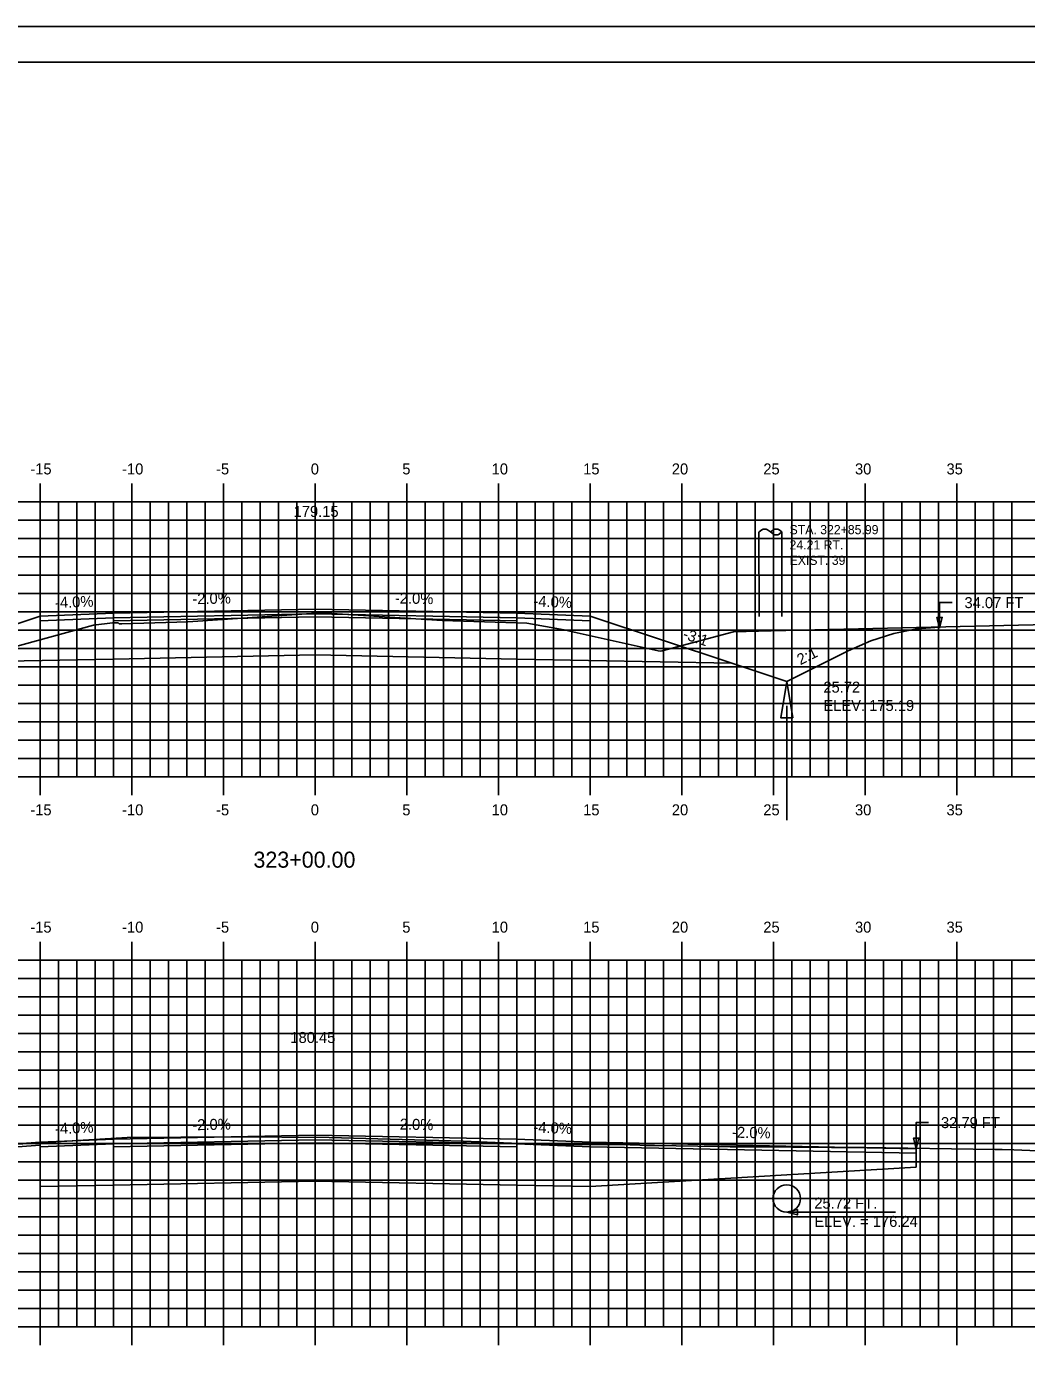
# Model space of a CAD drawing. Extents: x 1140094 to 1140264, y 608981 to 609091.
# Drawn here: x 1140161 to 1140215.5, y 609019.1 to 609091.3 of the extents above; entities that cross this region are included whole.
import ezdxf

# ---------------------------------------------------------------- set-up
doc = ezdxf.new("R2010")
doc.units = 0
for name, color, linetype in [('ANNOTATION', 7, 'Continuous'), ('BORDER', 7, 'Continuous'), ('D_Drainage_Culvert', 7, 'Continuous'), ('D_Drainage_Ditch_Line', 7, 'Continuous'), ('D_Roadway_Centerline', 7, 'Continuous'), ('D_Roadway_Centerline_Text', 7, 'Continuous'), ('D_Roadway_Edge_Shoulder', 7, 'Continuous'), ('D_Roadway_Edge_TW', 7, 'Continuous'), ('D_Roadway_Pavement', 7, 'Continuous'), ('D_Roadway_SlopeLines', 7, 'Continuous'), ('D_Roadway_SubGrade', 7, 'Continuous'), ('D_Text_Monospaced', 7, 'Continuous'), ('D_Text_Standard', 7, 'Continuous'), ('H_V ANNOTATION', 7, 'Continuous'), ('MAJOR', 7, 'Continuous'), ('MINOR', 7, 'Continuous'), ('PLOT BOUNDARY', 7, 'Continuous'), ('S_Roadway_Centerline', 7, 'Continuous'), ('S_Utilities_Pole_Power', 7, 'Continuous')]:
    doc.layers.add(name, color=color, linetype=linetype)

msp = doc.modelspace()

# ---------------------------------------------------------------- linework, layer by layer
for points in [[(1140146.431, 609056.645), (1140147.575, 609056.586), (1140148.719, 609056.38), (1140149.863, 609056.028), (1140151.007, 609055.529), (1140154.007, 609056.529), (1140161.73, 609059.104), (1140161.731, 609059.104), (1140165.731, 609059.264), (1140176.731, 609059.484), (1140187.731, 609059.264), (1140191.731, 609059.104), (1140199.455, 609056.529), (1140202.455, 609055.529), (1140205.798, 609057.201), (1140207.048, 609057.751), (1140208.298, 609058.153), (1140209.548, 609058.405), (1140210.798, 609058.508)], [(1140161.73, 609030.403), (1140161.731, 609030.403), (1140165.731, 609030.563), (1140176.731, 609030.783), (1140187.731, 609030.563), (1140191.731, 609030.403), (1140209.522, 609030.047)]]:
    msp.add_lwpolyline(points)
at = {"layer": 'BORDER'}
msp.add_lwpolyline([(1140101.732, 608984.335), (1140261.732, 608984.335), (1140261.732, 609089.335), (1140101.732, 609089.335)], close=True, dxfattribs=at)
at = {"layer": 'D_Drainage_Culvert'}
msp.add_circle((1140202.455, 609027.329), 0.75, dxfattribs=at)
at = {"layer": 'D_Drainage_Ditch_Line'}
msp.add_line((1140202.455, 609054.217), (1140202.455, 609047.974), dxfattribs=at)
msp.add_lwpolyline([(1140202.783, 609053.561), (1140202.127, 609053.561), (1140202.455, 609055.529)], close=True, dxfattribs=at)
at = {"layer": 'D_Roadway_Edge_Shoulder'}
for points in [[(1140165.731, 609059.264), (1140161.731, 609059.104), (1140161.731, 609058.854), (1140165.731, 609059.014)], [(1140187.731, 609059.264), (1140191.731, 609059.104), (1140191.731, 609058.854), (1140187.731, 609059.014)], [(1140165.731, 609030.563), (1140161.731, 609030.403), (1140161.731, 609030.153), (1140165.731, 609030.313)], [(1140187.731, 609030.563), (1140191.731, 609030.403), (1140191.731, 609030.153), (1140187.731, 609030.313)], [(1140161.731, 609030.403), (1140158.731, 609030.183), (1140158.744, 609030.016), (1140161.73, 609030.236)], [(1140191.731, 609030.403), (1140191.731, 609030.153), (1140209.522, 609029.797), (1140209.522, 609030.047)]]:
    msp.add_lwpolyline(points, close=True, dxfattribs=at)
at = {"layer": 'D_Roadway_Edge_TW'}
for points in [[(1140165.731, 609059.014), (1140165.731, 609059.264), (1140176.731, 609059.484), (1140187.731, 609059.264), (1140187.731, 609059.014), (1140176.731, 609059.234)], [(1140165.731, 609030.313), (1140165.731, 609030.563), (1140176.731, 609030.783), (1140187.731, 609030.563), (1140187.731, 609030.313), (1140176.731, 609030.533)]]:
    msp.add_lwpolyline(points, close=True, dxfattribs=at)
at = {"layer": 'D_Roadway_Pavement'}
for points in [[(1140165.731, 609058.847), (1140165.731, 609059.014), (1140176.731, 609059.234), (1140187.731, 609059.014), (1140187.731, 609058.847), (1140176.731, 609059.067)], [(1140165.731, 609030.146), (1140165.731, 609030.313), (1140176.731, 609030.533), (1140187.731, 609030.313), (1140187.731, 609030.146), (1140176.731, 609030.366)]]:
    msp.add_lwpolyline(points, close=True, dxfattribs=at)
at = {"layer": 'D_Roadway_SlopeLines'}
for points in [[(1140202.455, 609055.529), (1140205.798, 609057.201), (1140207.048, 609057.751), (1140208.298, 609058.153), (1140209.548, 609058.405), (1140210.798, 609058.508)], [(1140199.455, 609056.529), (1140202.455, 609055.529)]]:
    msp.add_lwpolyline(points, dxfattribs=at)
at = {"layer": 'D_Roadway_SubGrade'}
for points in [[(1140165.731, 609058.847), (1140165.731, 609059.014), (1140161.731, 609058.854), (1140161.731, 609059.104), (1140161.73, 609059.104), (1140154.007, 609056.529), (1140165.731, 609056.764)], [(1140165.731, 609056.764), (1140165.731, 609058.847), (1140176.731, 609059.067), (1140187.731, 609058.847), (1140187.731, 609056.764), (1140176.731, 609056.984)], [(1140187.731, 609058.847), (1140187.731, 609059.014), (1140191.731, 609058.854), (1140191.731, 609059.104), (1140191.732, 609059.104), (1140199.455, 609056.529), (1140187.731, 609056.764)], [(1140161.73, 609029.403), (1140161.731, 609027.983), (1140165.731, 609028.063), (1140165.731, 609030.146), (1140165.731, 609030.313), (1140161.731, 609030.153), (1140161.731, 609030.403), (1140161.73, 609030.403)], [(1140165.731, 609028.063), (1140165.731, 609030.146), (1140176.731, 609030.366), (1140187.731, 609030.146), (1140187.731, 609028.063), (1140176.731, 609028.283)], [(1140209.522, 609029.047), (1140209.522, 609030.047), (1140191.731, 609030.403), (1140191.731, 609030.153), (1140187.731, 609030.313), (1140187.731, 609030.146), (1140187.731, 609028.063), (1140191.731, 609027.983)]]:
    msp.add_lwpolyline(points, close=True, dxfattribs=at)
at = {"layer": 'D_Text_Standard'}
msp.add_line((1140203.961, 609026.579), (1140208.398, 609026.579), dxfattribs=at)
for points in [[(1140210.798, 609058.451), (1140210.792, 609059.84), (1140211.472, 609059.84)], [(1140209.522, 609030.047), (1140209.512, 609031.469), (1140210.192, 609031.469)], [(1140202.455, 609026.579), (1140203.281, 609026.579), (1140203.961, 609026.579)]]:
    msp.add_lwpolyline(points, dxfattribs=at)
for points in [[(1140210.798, 609058.451), (1140210.65, 609059.032), (1140210.941, 609059.034)], [(1140209.522, 609030.047), (1140209.373, 609030.628), (1140209.664, 609030.63)], [(1140202.455, 609026.579), (1140203.037, 609026.724), (1140203.037, 609026.433)]]:
    msp.add_lwpolyline(points, close=True, dxfattribs=at)
at = {"layer": 'MAJOR'}
for p, q in [((1140161.731, 609066.337), (1140161.731, 609065.335)), ((1140166.731, 609066.337), (1140166.731, 609065.335)), ((1140171.731, 609066.337), (1140171.731, 609065.335)), ((1140176.731, 609066.337), (1140176.731, 609065.335)), ((1140181.731, 609066.337), (1140181.731, 609065.335)), ((1140186.731, 609066.337), (1140186.731, 609065.335)), ((1140191.731, 609066.337), (1140191.731, 609065.335)), ((1140196.731, 609066.337), (1140196.731, 609065.335)), ((1140201.731, 609066.337), (1140201.731, 609065.335)), ((1140206.731, 609066.337), (1140206.731, 609065.335)), ((1140211.731, 609066.337), (1140211.731, 609065.335)), ((1140106.731, 609065.335), (1140246.731, 609065.335)), ((1140106.731, 609065.335), (1140246.731, 609065.335)), ((1140161.731, 609050.335), (1140161.731, 609065.335)), ((1140166.731, 609050.335), (1140166.731, 609065.335)), ((1140171.731, 609050.335), (1140171.731, 609065.335)), ((1140176.731, 609050.335), (1140176.731, 609065.335)), ((1140181.731, 609050.335), (1140181.731, 609065.335)), ((1140186.731, 609050.335), (1140186.731, 609065.335)), ((1140191.731, 609050.335), (1140191.731, 609065.335)), ((1140196.731, 609050.335), (1140196.731, 609065.335)), ((1140201.731, 609050.335), (1140201.731, 609065.335)), ((1140206.731, 609050.335), (1140206.731, 609065.335)), ((1140211.731, 609050.335), (1140211.731, 609065.335)), ((1140106.731, 609060.335), (1140246.731, 609060.335)), ((1140106.731, 609055.335), (1140246.731, 609055.335)), ((1140106.731, 609050.335), (1140246.731, 609050.335)), ((1140106.731, 609050.335), (1140246.731, 609050.335)), ((1140161.731, 609049.333), (1140161.731, 609050.335)), ((1140166.731, 609049.333), (1140166.731, 609050.335)), ((1140171.731, 609049.333), (1140171.731, 609050.335)), ((1140176.731, 609049.333), (1140176.731, 609050.335)), ((1140181.731, 609049.333), (1140181.731, 609050.335)), ((1140186.731, 609049.333), (1140186.731, 609050.335)), ((1140191.731, 609049.333), (1140191.731, 609050.335)), ((1140196.731, 609049.333), (1140196.731, 609050.335)), ((1140201.731, 609049.333), (1140201.731, 609050.335)), ((1140206.731, 609049.333), (1140206.731, 609050.335)), ((1140211.731, 609049.333), (1140211.731, 609050.335)), ((1140161.731, 609041.337), (1140161.731, 609040.335)), ((1140166.731, 609041.337), (1140166.731, 609040.335)), ((1140171.731, 609041.337), (1140171.731, 609040.335)), ((1140176.731, 609041.337), (1140176.731, 609040.335)), ((1140181.731, 609041.337), (1140181.731, 609040.335)), ((1140186.731, 609041.337), (1140186.731, 609040.335)), ((1140191.731, 609041.337), (1140191.731, 609040.335)), ((1140196.731, 609041.337), (1140196.731, 609040.335)), ((1140201.731, 609041.337), (1140201.731, 609040.335)), ((1140206.731, 609041.337), (1140206.731, 609040.335)), ((1140211.731, 609041.337), (1140211.731, 609040.335)), ((1140106.731, 609040.335), (1140246.731, 609040.335)), ((1140106.731, 609040.335), (1140246.731, 609040.335)), ((1140161.731, 609020.335), (1140161.731, 609040.335)), ((1140166.731, 609020.335), (1140166.731, 609040.335)), ((1140171.731, 609020.335), (1140171.731, 609040.335)), ((1140176.731, 609020.335), (1140176.731, 609040.335)), ((1140181.731, 609020.335), (1140181.731, 609040.335)), ((1140186.731, 609020.335), (1140186.731, 609040.335)), ((1140191.731, 609020.335), (1140191.731, 609040.335)), ((1140196.731, 609020.335), (1140196.731, 609040.335)), ((1140201.731, 609020.335), (1140201.731, 609040.335)), ((1140206.731, 609020.335), (1140206.731, 609040.335)), ((1140211.731, 609020.335), (1140211.731, 609040.335)), ((1140106.731, 609035.335), (1140246.731, 609035.335)), ((1140106.731, 609030.335), (1140246.731, 609030.335)), ((1140106.731, 609025.335), (1140246.731, 609025.335)), ((1140106.731, 609020.335), (1140246.731, 609020.335)), ((1140106.731, 609020.335), (1140246.731, 609020.335)), ((1140161.731, 609019.333), (1140161.731, 609020.335)), ((1140166.731, 609019.333), (1140166.731, 609020.335)), ((1140171.731, 609019.333), (1140171.731, 609020.335)), ((1140176.731, 609019.333), (1140176.731, 609020.335)), ((1140181.731, 609019.333), (1140181.731, 609020.335)), ((1140186.731, 609019.333), (1140186.731, 609020.335)), ((1140191.731, 609019.333), (1140191.731, 609020.335)), ((1140196.731, 609019.333), (1140196.731, 609020.335)), ((1140201.731, 609019.333), (1140201.731, 609020.335)), ((1140206.731, 609019.333), (1140206.731, 609020.335)), ((1140211.731, 609019.333), (1140211.731, 609020.335))]:
    msp.add_line(p, q, dxfattribs=at)
at = {"layer": 'MINOR'}
for p, q in [((1140162.731, 609050.335), (1140162.731, 609065.335)), ((1140163.731, 609050.335), (1140163.731, 609065.335)), ((1140164.731, 609050.335), (1140164.731, 609065.335)), ((1140165.731, 609050.335), (1140165.731, 609065.335)), ((1140167.731, 609050.335), (1140167.731, 609065.335)), ((1140168.731, 609050.335), (1140168.731, 609065.335)), ((1140169.731, 609050.335), (1140169.731, 609065.335)), ((1140170.731, 609050.335), (1140170.731, 609065.335)), ((1140172.731, 609050.335), (1140172.731, 609065.335)), ((1140173.731, 609050.335), (1140173.731, 609065.335)), ((1140174.731, 609050.335), (1140174.731, 609065.335)), ((1140175.731, 609050.335), (1140175.731, 609065.335)), ((1140177.731, 609050.335), (1140177.731, 609065.335)), ((1140178.731, 609050.335), (1140178.731, 609065.335)), ((1140179.731, 609050.335), (1140179.731, 609065.335)), ((1140180.731, 609050.335), (1140180.731, 609065.335)), ((1140182.731, 609050.335), (1140182.731, 609065.335)), ((1140183.731, 609050.335), (1140183.731, 609065.335)), ((1140184.731, 609050.335), (1140184.731, 609065.335)), ((1140185.731, 609050.335), (1140185.731, 609065.335)), ((1140187.731, 609050.335), (1140187.731, 609065.335)), ((1140188.731, 609050.335), (1140188.731, 609065.335)), ((1140189.731, 609050.335), (1140189.731, 609065.335)), ((1140190.731, 609050.335), (1140190.731, 609065.335)), ((1140192.731, 609050.335), (1140192.731, 609065.335)), ((1140193.731, 609050.335), (1140193.731, 609065.335)), ((1140194.731, 609050.335), (1140194.731, 609065.335)), ((1140195.731, 609050.335), (1140195.731, 609065.335)), ((1140197.731, 609050.335), (1140197.731, 609065.335)), ((1140198.731, 609050.335), (1140198.731, 609065.335)), ((1140199.731, 609050.335), (1140199.731, 609065.335)), ((1140200.731, 609050.335), (1140200.731, 609065.335)), ((1140202.731, 609050.335), (1140202.731, 609065.335)), ((1140203.731, 609050.335), (1140203.731, 609065.335)), ((1140204.731, 609050.335), (1140204.731, 609065.335)), ((1140205.731, 609050.335), (1140205.731, 609065.335)), ((1140207.731, 609050.335), (1140207.731, 609065.335)), ((1140208.731, 609050.335), (1140208.731, 609065.335)), ((1140209.731, 609050.335), (1140209.731, 609065.335)), ((1140210.731, 609050.335), (1140210.731, 609065.335)), ((1140212.731, 609050.335), (1140212.731, 609065.335)), ((1140213.731, 609050.335), (1140213.731, 609065.335)), ((1140214.731, 609050.335), (1140214.731, 609065.335)), ((1140106.731, 609064.335), (1140246.731, 609064.335)), ((1140106.731, 609063.335), (1140246.731, 609063.335)), ((1140106.731, 609062.335), (1140246.731, 609062.335)), ((1140106.731, 609061.335), (1140246.731, 609061.335)), ((1140106.731, 609059.335), (1140246.731, 609059.335)), ((1140106.731, 609058.335), (1140246.731, 609058.335)), ((1140106.731, 609057.335), (1140246.731, 609057.335)), ((1140106.731, 609056.335), (1140246.731, 609056.335)), ((1140106.731, 609054.335), (1140246.731, 609054.335)), ((1140106.731, 609053.335), (1140246.731, 609053.335)), ((1140106.731, 609052.335), (1140246.731, 609052.335)), ((1140106.731, 609051.335), (1140246.731, 609051.335)), ((1140162.731, 609020.335), (1140162.731, 609040.335)), ((1140163.731, 609020.335), (1140163.731, 609040.335)), ((1140164.731, 609020.335), (1140164.731, 609040.335)), ((1140165.731, 609020.335), (1140165.731, 609040.335)), ((1140167.731, 609020.335), (1140167.731, 609040.335)), ((1140168.731, 609020.335), (1140168.731, 609040.335)), ((1140169.731, 609020.335), (1140169.731, 609040.335)), ((1140170.731, 609020.335), (1140170.731, 609040.335)), ((1140172.731, 609020.335), (1140172.731, 609040.335)), ((1140173.731, 609020.335), (1140173.731, 609040.335)), ((1140174.731, 609020.335), (1140174.731, 609040.335)), ((1140175.731, 609020.335), (1140175.731, 609040.335)), ((1140177.731, 609020.335), (1140177.731, 609040.335)), ((1140178.731, 609020.335), (1140178.731, 609040.335)), ((1140179.731, 609020.335), (1140179.731, 609040.335)), ((1140180.731, 609020.335), (1140180.731, 609040.335)), ((1140182.731, 609020.335), (1140182.731, 609040.335)), ((1140183.731, 609020.335), (1140183.731, 609040.335)), ((1140184.731, 609020.335), (1140184.731, 609040.335)), ((1140185.731, 609020.335), (1140185.731, 609040.335)), ((1140187.731, 609020.335), (1140187.731, 609040.335)), ((1140188.731, 609020.335), (1140188.731, 609040.335)), ((1140189.731, 609020.335), (1140189.731, 609040.335)), ((1140190.731, 609020.335), (1140190.731, 609040.335)), ((1140192.731, 609020.335), (1140192.731, 609040.335)), ((1140193.731, 609020.335), (1140193.731, 609040.335)), ((1140194.731, 609020.335), (1140194.731, 609040.335)), ((1140195.731, 609020.335), (1140195.731, 609040.335)), ((1140197.731, 609020.335), (1140197.731, 609040.335)), ((1140198.731, 609020.335), (1140198.731, 609040.335)), ((1140199.731, 609020.335), (1140199.731, 609040.335)), ((1140200.731, 609020.335), (1140200.731, 609040.335)), ((1140202.731, 609020.335), (1140202.731, 609040.335)), ((1140203.731, 609020.335), (1140203.731, 609040.335)), ((1140204.731, 609020.335), (1140204.731, 609040.335)), ((1140205.731, 609020.335), (1140205.731, 609040.335)), ((1140207.731, 609020.335), (1140207.731, 609040.335)), ((1140208.731, 609020.335), (1140208.731, 609040.335)), ((1140209.731, 609020.335), (1140209.731, 609040.335)), ((1140210.731, 609020.335), (1140210.731, 609040.335)), ((1140212.731, 609020.335), (1140212.731, 609040.335)), ((1140213.731, 609020.335), (1140213.731, 609040.335)), ((1140214.731, 609020.335), (1140214.731, 609040.335)), ((1140106.731, 609039.335), (1140246.731, 609039.335)), ((1140106.731, 609038.335), (1140246.731, 609038.335)), ((1140106.731, 609037.335), (1140246.731, 609037.335)), ((1140106.731, 609036.335), (1140246.731, 609036.335)), ((1140106.731, 609034.335), (1140246.731, 609034.335)), ((1140106.731, 609033.335), (1140246.731, 609033.335)), ((1140106.731, 609032.335), (1140246.731, 609032.335)), ((1140106.731, 609031.335), (1140246.731, 609031.335)), ((1140106.731, 609029.335), (1140246.731, 609029.335)), ((1140106.731, 609028.335), (1140246.731, 609028.335)), ((1140106.731, 609027.335), (1140246.731, 609027.335)), ((1140106.731, 609026.335), (1140246.731, 609026.335)), ((1140106.731, 609024.335), (1140246.731, 609024.335)), ((1140106.731, 609023.335), (1140246.731, 609023.335)), ((1140106.731, 609022.335), (1140246.731, 609022.335)), ((1140106.731, 609021.335), (1140246.731, 609021.335))]:
    msp.add_line(p, q, dxfattribs=at)
at = {"layer": 'PLOT BOUNDARY'}
msp.add_lwpolyline([(1140093.638, 608981.276), (1140263.638, 608981.276), (1140263.638, 609091.276), (1140093.638, 609091.276)], close=True, dxfattribs=at)
at = {"layer": 'S_Roadway_Centerline'}
for points in [[(1140145.884, 609056.638), (1140156.704, 609056.772), (1140158.401, 609056.894), (1140164.633, 609058.607), (1140165.669, 609058.733), (1140165.972, 609058.746), (1140166.042, 609058.687), (1140166.187, 609058.687), (1140169.779, 609058.79), (1140177.071, 609059.28), (1140183.662, 609058.861), (1140188.271, 609058.728), (1140190.31, 609058.358), (1140191.022, 609058.194), (1140195.441, 609057.212), (1140195.554, 609057.192), (1140195.653, 609057.202), (1140199.545, 609058.254), (1140201.609, 609058.298), (1140221.444, 609058.751), (1140223.681, 609058.778), (1140246.731, 609058.72)], [(1140158.37, 609030.161), (1140166.477, 609030.655), (1140172.308, 609030.694), (1140177.498, 609030.665), (1140184.811, 609030.454), (1140188.313, 609030.303), (1140188.478, 609030.278), (1140188.976, 609030.285), (1140189.381, 609030.286), (1140189.686, 609030.285), (1140190.388, 609030.276), (1140193.913, 609030.25), (1140194.439, 609030.237), (1140194.742, 609030.228), (1140195.248, 609030.214), (1140198.787, 609030.168), (1140199.367, 609030.153), (1140200.067, 609030.144), (1140200.597, 609030.14), (1140204.903, 609030.116), (1140205.752, 609030.114), (1140206.671, 609030.11), (1140213.825, 609030.005), (1140214.212, 609030), (1140214.845, 609029.983), (1140217.475, 609029.884)]]:
    msp.add_lwpolyline(points, dxfattribs=at)
at = {"layer": 'S_Utilities_Pole_Power'}
for p, q in [((1140200.943, 609063.694), (1140201.099, 609063.805)), ((1140201.412, 609063.805), (1140201.568, 609063.694)), ((1140201.725, 609063.805), (1140201.568, 609063.694)), ((1140202.193, 609063.694), (1140202.037, 609063.805)), ((1140200.943, 609059.075), (1140200.94, 609063.694)), ((1140201.568, 609063.694), (1140201.725, 609063.583)), ((1140202.037, 609063.583), (1140202.193, 609063.694)), ((1140202.193, 609059.075), (1140202.19, 609063.694))]:
    msp.add_line(p, q, dxfattribs=at)
for centre, start, end in [((1140201.256, 609063.584), 90, 125.26439), ((1140201.256, 609063.584), 54.73561, 90), ((1140201.881, 609063.584), 90, 125.26439), ((1140201.881, 609063.584), 54.73561, 90), ((1140201.881, 609063.805), 234.73561, 270), ((1140201.881, 609063.805), 270, 305.26439)]:
    msp.add_arc(centre, 0.271, start, end, dxfattribs=at)

# ---------------------------------------------------------------- texts
at = {"layer": 'ANNOTATION'}
for s, rotation, p in [('-4.0%', 2.29061, (1140162.547, 609059.537)), ('-2.0%', 1.14576, (1140170.034, 609059.75)), ('-2.0%', 358.85424, (1140181.074, 609059.797)), ('-4.0%', 357.70939, (1140188.627, 609059.629)), ('-3:1', 341.56521, (1140196.743, 609057.888)), ('2:1', 26.56505, (1140203.199, 609056.42)), ('-4.0%', 2.29061, (1140162.547, 609030.837)), ('-2.0%', 1.14576, (1140170.034, 609031.049)), ('-2.0%', 358.85424, (1140181.074, 609031.096)), ('-4.0%', 357.70939, (1140188.627, 609030.928)), ('-2.0%', 358.85424, (1140199.47, 609030.649))]:
    msp.add_text(s, height=0.6, rotation=rotation, dxfattribs=at).set_placement(p)
at = {"layer": 'D_Roadway_Centerline'}
for s, p in [('C', (1140176.726, 609059.484)), ('L', (1140176.731, 609059.477)), ('C', (1140176.726, 609030.783)), ('L', (1140176.731, 609030.776))]:
    msp.add_text(s, height=0.0146, dxfattribs=at).set_placement(p)
at = {"layer": 'D_Roadway_Centerline_Text'}
for s, p in [('179.15', (1140175.552, 609064.516)), ('180.45', (1140175.375, 609035.815))]:
    msp.add_text(s, height=0.6, dxfattribs=at).set_placement(p)
at = {"layer": 'D_Text_Monospaced'}
for s, height, p in [('STA. 322+85.99', 0.49998, (1140202.61, 609063.573)), ('24.21 RT.', 0.5, (1140202.61, 609062.739)), ('EXIST. 39', 0.5, (1140202.61, 609061.899))]:
    msp.add_text(s, height=height, dxfattribs=at).set_placement(p)
at = {"layer": 'D_Text_Standard'}
for s, p in [('34.07 FT', (1140212.152, 609059.54)), ('25.72', (1140204.455, 609054.929)), ('ELEV. 175.19', (1140204.455, 609053.927)), ('32.79 FT', (1140210.872, 609031.169)), ('25.72 FT.', (1140203.961, 609026.779)), ('ELEV. = 176.24', (1140203.961, 609025.779))]:
    msp.add_text(s, height=0.6, dxfattribs=at).set_placement(p)
at = {"layer": 'H_V ANNOTATION'}
for s, height, p in [('-15', 0.6, (1140161.188, 609066.835)), ('-10', 0.6, (1140166.196, 609066.835)), ('-5', 0.6, (1140171.322, 609066.835)), ('0', 0.6, (1140176.49, 609066.835)), ('5', 0.6, (1140181.482, 609066.835)), ('10', 0.6, (1140186.357, 609066.835)), ('15', 0.6, (1140191.349, 609066.835)), ('20', 0.6, (1140196.185, 609066.835)), ('25', 0.6, (1140201.177, 609066.835)), ('30', 0.6, (1140206.18, 609066.835)), ('35', 0.6, (1140211.172, 609066.835)), ('-15', 0.6, (1140161.188, 609048.235)), ('-10', 0.6, (1140166.196, 609048.235)), ('-5', 0.6, (1140171.322, 609048.235)), ('0', 0.6, (1140176.49, 609048.235)), ('5', 0.6, (1140181.482, 609048.235)), ('10', 0.6, (1140186.357, 609048.235)), ('15', 0.6, (1140191.349, 609048.235)), ('20', 0.6, (1140196.185, 609048.235)), ('25', 0.6, (1140201.177, 609048.235)), ('30', 0.6, (1140206.18, 609048.235)), ('35', 0.6, (1140211.172, 609048.235)), ('323+00.00', 0.875, (1140173.36, 609045.378)), ('-15', 0.6, (1140161.188, 609041.835)), ('-10', 0.6, (1140166.196, 609041.835)), ('-5', 0.6, (1140171.322, 609041.835)), ('0', 0.6, (1140176.49, 609041.835)), ('5', 0.6, (1140181.482, 609041.835)), ('10', 0.6, (1140186.357, 609041.835)), ('15', 0.6, (1140191.349, 609041.835)), ('20', 0.6, (1140196.185, 609041.835)), ('25', 0.6, (1140201.177, 609041.835)), ('30', 0.6, (1140206.18, 609041.835)), ('35', 0.6, (1140211.172, 609041.835))]:
    msp.add_text(s, height=height, dxfattribs=at).set_placement(p)
at = {"layer": 'S_Roadway_Centerline'}
for s, p in [('C', (1140177.066, 609059.28)), ('L', (1140177.071, 609059.272)), ('C', (1140177.493, 609030.665)), ('L', (1140177.498, 609030.658))]:
    msp.add_text(s, height=0.0146, dxfattribs=at).set_placement(p)

doc.saveas('drawing.dxf')
